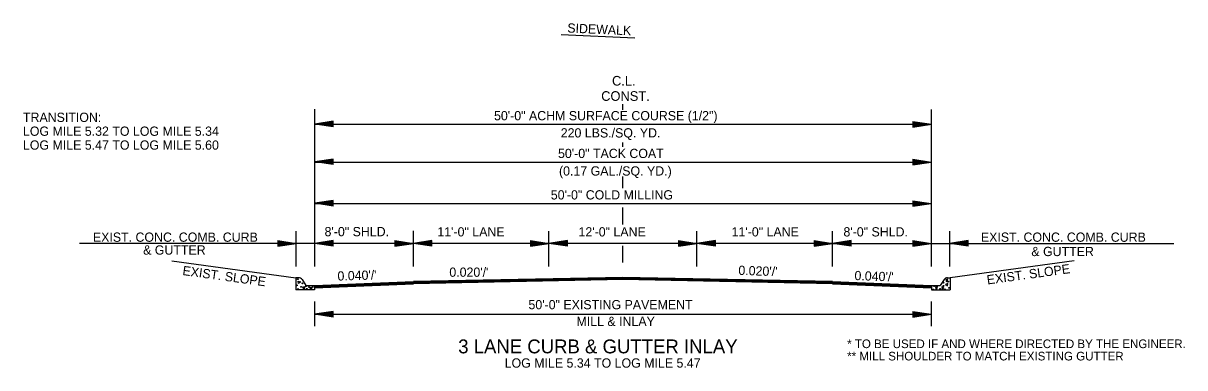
# Model space of a CAD drawing. Extents: x 544199 to 1930787, y -1968972 to 596640.
# Drawn here: x 551509 to 552451, y -1949022 to -1948742 of the extents above; entities that cross this region are included whole.
import ezdxf

# ---------------------------------------------------------------- set-up
doc = ezdxf.new("R2010")
doc.units = 0
for name, color, linetype in [('R_Border', 7, 'Continuous'), ('R_Border Prem', 7, 'Continuous'), ('R_Draft', 7, 'Continuous')]:
    doc.layers.add(name, color=color, linetype=linetype)

msp = doc.modelspace()

# ---------------------------------------------------------------- linework, layer by layer
at = {"layer": 'R_Border'}
msp.add_line((551945.52, -1948751.53), (552005.47, -1948754.13), dxfattribs=at)
at = {"layer": 'R_Draft'}
for p, q in [((551745.7, -1948812.01), (551745.7, -1948939.44)), ((551995.74, -1948812.46), (551995.74, -1948808.05)), ((551760.79, -1948821.8), (551745.79, -1948824.05)), ((551760.79, -1948822.18), (551748.29, -1948824.05)), ((551760.79, -1948822.56), (551750.87, -1948824.05)), ((551760.79, -1948826.3), (551760.79, -1948821.8)), ((552230.79, -1948821.97), (552245.79, -1948824.22)), ((552230.79, -1948821.97), (552230.79, -1948826.47)), ((552230.79, -1948822.35), (552243.28, -1948824.22)), ((552230.79, -1948822.73), (552240.7, -1948824.22)), ((551745.7, -1948824.22), (552245.7, -1948824.22)), ((551760.79, -1948826.3), (551745.79, -1948824.05)), ((551760.79, -1948825.93), (551748.29, -1948824.05)), ((551760.79, -1948825.55), (551750.87, -1948824.05)), ((551760.79, -1948822.94), (551753.37, -1948824.05)), ((551760.79, -1948825.17), (551753.37, -1948824.05)), ((551760.79, -1948823.32), (551755.91, -1948824.05)), ((551760.79, -1948824.78), (551755.91, -1948824.05)), ((551760.79, -1948823.7), (551758.42, -1948824.05)), ((551760.79, -1948824.41), (551758.42, -1948824.05)), ((552230.79, -1948823.11), (552238.21, -1948824.22)), ((552230.79, -1948823.5), (552235.66, -1948824.22)), ((552230.79, -1948823.87), (552233.16, -1948824.22)), ((552230.79, -1948826.47), (552245.79, -1948824.22)), ((552230.79, -1948824.96), (552235.66, -1948824.22)), ((552230.79, -1948825.72), (552240.7, -1948824.22)), ((552230.79, -1948826.1), (552243.28, -1948824.22)), ((552230.79, -1948825.34), (552238.21, -1948824.22)), ((552230.79, -1948824.58), (552233.16, -1948824.22)), ((551995.74, -1948842.59), (551995.74, -1948838.92)), ((551745.7, -1948854.82), (552245.7, -1948854.82)), ((551760.74, -1948852.4), (551745.74, -1948854.65)), ((551760.74, -1948856.9), (551745.74, -1948854.65)), ((551760.74, -1948852.77), (551748.25, -1948854.65)), ((551760.74, -1948856.52), (551748.25, -1948854.65)), ((551760.74, -1948853.16), (551750.83, -1948854.65)), ((551760.74, -1948856.14), (551750.83, -1948854.65)), ((551760.74, -1948853.53), (551753.32, -1948854.65)), ((551760.74, -1948855.77), (551753.32, -1948854.65)), ((551760.74, -1948853.91), (551755.87, -1948854.65)), ((551760.74, -1948855.38), (551755.87, -1948854.65)), ((551760.74, -1948854.3), (551758.37, -1948854.65)), ((551760.74, -1948855), (551758.37, -1948854.65)), ((551760.74, -1948856.9), (551760.74, -1948852.4)), ((552230.74, -1948852.57), (552245.74, -1948854.82)), ((552230.74, -1948852.57), (552230.74, -1948857.07)), ((552230.74, -1948852.95), (552243.24, -1948854.82)), ((552230.74, -1948853.33), (552240.66, -1948854.82)), ((552230.74, -1948853.7), (552238.16, -1948854.82)), ((552230.74, -1948854.09), (552235.62, -1948854.82)), ((552230.74, -1948854.47), (552233.11, -1948854.82)), ((552230.74, -1948857.07), (552245.74, -1948854.82)), ((552230.74, -1948855.56), (552235.62, -1948854.82)), ((552230.74, -1948856.31), (552240.66, -1948854.82)), ((552230.74, -1948856.7), (552243.24, -1948854.82)), ((552230.74, -1948855.94), (552238.16, -1948854.82)), ((552230.74, -1948855.17), (552233.11, -1948854.82)), ((551995.74, -1948875.95), (551995.74, -1948866.65)), ((551745.7, -1948888.42), (552245.7, -1948888.42)), ((551760.74, -1948886), (551745.74, -1948888.25)), ((551760.74, -1948890.5), (551745.74, -1948888.25)), ((551760.74, -1948886.37), (551748.25, -1948888.25)), ((551760.74, -1948890.12), (551748.25, -1948888.25)), ((551760.74, -1948886.76), (551750.83, -1948888.25)), ((551760.74, -1948889.74), (551750.83, -1948888.25)), ((551760.74, -1948887.13), (551753.32, -1948888.25)), ((551760.74, -1948889.37), (551753.32, -1948888.25)), ((551760.74, -1948887.51), (551755.87, -1948888.25)), ((551760.74, -1948888.98), (551755.87, -1948888.25)), ((551760.74, -1948887.9), (551758.37, -1948888.25)), ((551760.74, -1948888.6), (551758.37, -1948888.25)), ((551760.74, -1948890.5), (551760.74, -1948886)), ((552230.74, -1948886.17), (552245.74, -1948888.42)), ((552230.74, -1948886.17), (552230.74, -1948890.67)), ((552230.74, -1948886.54), (552243.24, -1948888.42)), ((552230.74, -1948886.93), (552240.66, -1948888.42)), ((552230.74, -1948887.3), (552238.16, -1948888.42)), ((552230.74, -1948887.69), (552235.62, -1948888.42)), ((552230.74, -1948888.07), (552233.11, -1948888.42)), ((552230.74, -1948890.67), (552245.74, -1948888.42)), ((552230.74, -1948889.15), (552235.62, -1948888.42)), ((552230.74, -1948889.91), (552240.66, -1948888.42)), ((552230.74, -1948890.29), (552243.24, -1948888.42)), ((552230.74, -1948889.54), (552238.16, -1948888.42)), ((552230.74, -1948888.77), (552233.11, -1948888.42)), ((551995.74, -1948905.39), (551995.74, -1948891.57)), ((551730.74, -1948939.61), (551730.74, -1948910.89)), ((551825.74, -1948939.44), (551825.74, -1948910.72)), ((551935.74, -1948939.44), (551935.74, -1948910.89)), ((552055.67, -1948920.78), (552055.67, -1948910.89)), ((552055.74, -1948939.44), (552055.74, -1948910.89)), ((552165.74, -1948939.43), (552165.74, -1948910.88)), ((552260.74, -1948939.61), (552260.74, -1948910.89)), ((551745.74, -1948920.78), (551554.93, -1948920.78)), ((551715.73, -1948918.53), (551730.73, -1948920.78)), ((551715.73, -1948918.53), (551715.73, -1948923.03)), ((551715.73, -1948918.9), (551728.23, -1948920.78)), ((551715.73, -1948919.29), (551725.65, -1948920.78)), ((551715.73, -1948919.66), (551723.15, -1948920.78)), ((551715.73, -1948920.05), (551720.61, -1948920.78)), ((551715.73, -1948920.43), (551718.1, -1948920.78)), ((551715.73, -1948923.03), (551730.73, -1948920.78)), ((551715.73, -1948921.51), (551720.61, -1948920.78)), ((551715.73, -1948922.27), (551725.65, -1948920.78)), ((551715.73, -1948922.65), (551728.23, -1948920.78)), ((551715.73, -1948921.9), (551723.15, -1948920.78)), ((551715.73, -1948921.13), (551718.1, -1948920.78)), ((551760.74, -1948918.53), (551745.74, -1948920.78)), ((551825.74, -1948920.78), (551745.74, -1948920.78)), ((551760.74, -1948923.03), (551745.74, -1948920.78)), ((551760.74, -1948918.9), (551748.25, -1948920.78)), ((551760.74, -1948922.65), (551748.25, -1948920.78)), ((551760.74, -1948919.29), (551750.83, -1948920.78)), ((551760.74, -1948922.27), (551750.83, -1948920.78)), ((551760.74, -1948919.66), (551753.32, -1948920.78)), ((551760.74, -1948921.9), (551753.32, -1948920.78)), ((551760.74, -1948920.04), (551755.87, -1948920.78)), ((551760.74, -1948921.51), (551755.87, -1948920.78)), ((551760.74, -1948920.43), (551758.37, -1948920.78)), ((551760.74, -1948921.13), (551758.37, -1948920.78)), ((551760.74, -1948923.03), (551760.74, -1948918.53)), ((551810.74, -1948918.53), (551825.74, -1948920.78)), ((551810.74, -1948918.53), (551810.74, -1948923.03)), ((551810.74, -1948918.9), (551823.24, -1948920.78)), ((551810.74, -1948919.29), (551820.66, -1948920.78)), ((551810.74, -1948919.66), (551818.16, -1948920.78)), ((551810.74, -1948920.05), (551815.62, -1948920.78)), ((551810.74, -1948920.43), (551813.11, -1948920.78)), ((551810.74, -1948923.03), (551825.74, -1948920.78)), ((551810.74, -1948921.51), (551815.62, -1948920.78)), ((551810.74, -1948922.27), (551820.66, -1948920.78)), ((551810.74, -1948922.65), (551823.24, -1948920.78)), ((551810.74, -1948921.9), (551818.16, -1948920.78)), ((551810.74, -1948921.13), (551813.11, -1948920.78)), ((551840.74, -1948918.53), (551825.74, -1948920.78)), ((551935.74, -1948920.78), (551825.74, -1948920.78)), ((551840.74, -1948923.03), (551825.74, -1948920.78)), ((551840.74, -1948918.9), (551828.25, -1948920.78)), ((551840.74, -1948922.65), (551828.25, -1948920.78)), ((551840.74, -1948919.29), (551830.83, -1948920.78)), ((551840.74, -1948922.27), (551830.83, -1948920.78)), ((551840.74, -1948919.66), (551833.32, -1948920.78)), ((551840.74, -1948921.9), (551833.32, -1948920.78)), ((551840.74, -1948920.04), (551835.87, -1948920.78)), ((551840.74, -1948921.51), (551835.87, -1948920.78)), ((551840.74, -1948920.43), (551838.37, -1948920.78)), ((551840.74, -1948921.13), (551838.37, -1948920.78)), ((551840.74, -1948923.03), (551840.74, -1948918.53)), ((551920.74, -1948918.53), (551935.74, -1948920.78)), ((551920.74, -1948918.53), (551920.74, -1948923.03)), ((551920.74, -1948918.9), (551933.24, -1948920.78)), ((551920.74, -1948919.29), (551930.66, -1948920.78)), ((551920.74, -1948919.66), (551928.16, -1948920.78)), ((551920.74, -1948920.05), (551925.62, -1948920.78)), ((551920.74, -1948920.43), (551923.11, -1948920.78)), ((551920.74, -1948923.03), (551935.74, -1948920.78)), ((551920.74, -1948921.51), (551925.62, -1948920.78)), ((551920.74, -1948922.27), (551930.66, -1948920.78)), ((551920.74, -1948922.65), (551933.24, -1948920.78)), ((551920.74, -1948921.9), (551928.16, -1948920.78)), ((551920.74, -1948921.13), (551923.11, -1948920.78)), ((551950.74, -1948918.53), (551935.74, -1948920.78)), ((552055.74, -1948920.78), (551935.74, -1948920.78)), ((551950.74, -1948923.03), (551935.74, -1948920.78)), ((551950.74, -1948918.9), (551938.25, -1948920.78)), ((551950.74, -1948922.65), (551938.25, -1948920.78)), ((551950.74, -1948919.29), (551940.83, -1948920.78)), ((551950.74, -1948922.27), (551940.83, -1948920.78)), ((551950.74, -1948919.66), (551943.32, -1948920.78)), ((551950.74, -1948921.9), (551943.32, -1948920.78)), ((551950.74, -1948920.04), (551945.87, -1948920.78)), ((551950.74, -1948921.51), (551945.87, -1948920.78)), ((551950.74, -1948920.43), (551948.37, -1948920.78)), ((551950.74, -1948921.13), (551948.37, -1948920.78)), ((551950.74, -1948923.03), (551950.74, -1948918.53)), ((551995.74, -1948936.19), (551995.74, -1948922.9)), ((552040.74, -1948918.53), (552055.74, -1948920.78)), ((552040.74, -1948918.53), (552040.74, -1948923.03)), ((552040.74, -1948918.9), (552053.24, -1948920.78)), ((552040.74, -1948919.29), (552050.66, -1948920.78)), ((552040.74, -1948919.66), (552048.16, -1948920.78)), ((552040.74, -1948920.05), (552045.62, -1948920.78)), ((552040.74, -1948920.43), (552043.11, -1948920.78)), ((552040.74, -1948923.03), (552055.74, -1948920.78)), ((552040.74, -1948921.51), (552045.62, -1948920.78)), ((552040.74, -1948922.27), (552050.66, -1948920.78)), ((552040.74, -1948922.65), (552053.24, -1948920.78)), ((552040.74, -1948921.9), (552048.16, -1948920.78)), ((552040.74, -1948921.13), (552043.11, -1948920.78)), ((552055.67, -1948939.44), (552055.67, -1948920.78)), ((552070.74, -1948918.53), (552055.74, -1948920.78)), ((552165.74, -1948920.78), (552055.74, -1948920.78)), ((552070.74, -1948923.03), (552055.74, -1948920.78)), ((552070.74, -1948918.9), (552058.25, -1948920.78)), ((552070.74, -1948922.65), (552058.25, -1948920.78)), ((552070.74, -1948919.29), (552060.83, -1948920.78)), ((552070.74, -1948922.27), (552060.83, -1948920.78)), ((552070.74, -1948919.66), (552063.32, -1948920.78)), ((552070.74, -1948921.9), (552063.32, -1948920.78)), ((552070.74, -1948920.04), (552065.87, -1948920.78)), ((552070.74, -1948921.51), (552065.87, -1948920.78)), ((552070.74, -1948920.43), (552068.37, -1948920.78)), ((552070.74, -1948921.13), (552068.37, -1948920.78)), ((552070.74, -1948923.03), (552070.74, -1948918.53)), ((552150.74, -1948918.53), (552165.74, -1948920.78)), ((552150.74, -1948918.53), (552150.74, -1948923.03)), ((552150.74, -1948918.9), (552163.24, -1948920.78)), ((552150.74, -1948919.29), (552160.66, -1948920.78)), ((552150.74, -1948919.66), (552158.16, -1948920.78)), ((552150.74, -1948920.05), (552155.62, -1948920.78)), ((552150.74, -1948920.43), (552153.11, -1948920.78)), ((552150.74, -1948923.03), (552165.74, -1948920.78)), ((552150.74, -1948921.51), (552155.62, -1948920.78)), ((552150.74, -1948922.27), (552160.66, -1948920.78)), ((552150.74, -1948922.65), (552163.24, -1948920.78)), ((552150.74, -1948921.9), (552158.16, -1948920.78)), ((552150.74, -1948921.13), (552153.11, -1948920.78)), ((552180.74, -1948918.53), (552165.74, -1948920.78)), ((552165.74, -1948920.78), (552245.74, -1948920.78)), ((552180.74, -1948923.03), (552165.74, -1948920.78)), ((552180.74, -1948918.9), (552168.25, -1948920.78)), ((552180.74, -1948922.65), (552168.25, -1948920.78)), ((552180.74, -1948919.29), (552170.83, -1948920.78)), ((552180.74, -1948922.27), (552170.83, -1948920.78)), ((552180.74, -1948919.66), (552173.32, -1948920.78)), ((552180.74, -1948921.9), (552173.32, -1948920.78)), ((552180.74, -1948920.04), (552175.87, -1948920.78)), ((552180.74, -1948921.51), (552175.87, -1948920.78)), ((552180.74, -1948920.43), (552178.37, -1948920.78)), ((552180.74, -1948921.13), (552178.37, -1948920.78)), ((552180.74, -1948923.03), (552180.74, -1948918.53)), ((552230.74, -1948918.53), (552245.74, -1948920.78)), ((552230.74, -1948918.53), (552230.74, -1948923.03)), ((552230.74, -1948918.9), (552243.24, -1948920.78)), ((552230.74, -1948919.29), (552240.66, -1948920.78)), ((552230.74, -1948919.66), (552238.16, -1948920.78)), ((552230.74, -1948920.05), (552235.62, -1948920.78)), ((552230.74, -1948920.43), (552233.11, -1948920.78)), ((552230.74, -1948923.03), (552245.74, -1948920.78)), ((552230.74, -1948921.51), (552235.62, -1948920.78)), ((552230.74, -1948922.27), (552240.66, -1948920.78)), ((552230.74, -1948922.65), (552243.24, -1948920.78)), ((552230.74, -1948921.9), (552238.16, -1948920.78)), ((552230.74, -1948921.13), (552233.11, -1948920.78)), ((552245.74, -1948920.78), (552442.42, -1948920.78)), ((552275.74, -1948918.53), (552260.74, -1948920.78)), ((552275.74, -1948923.03), (552260.74, -1948920.78)), ((552275.74, -1948918.9), (552263.25, -1948920.78)), ((552275.74, -1948922.65), (552263.25, -1948920.78)), ((552275.74, -1948919.29), (552265.83, -1948920.78)), ((552275.74, -1948922.27), (552265.83, -1948920.78)), ((552275.74, -1948919.66), (552268.32, -1948920.78)), ((552275.74, -1948921.9), (552268.32, -1948920.78)), ((552275.74, -1948920.04), (552270.87, -1948920.78)), ((552275.74, -1948921.51), (552270.87, -1948920.78)), ((552275.74, -1948920.43), (552273.37, -1948920.78)), ((552275.74, -1948921.13), (552273.37, -1948920.78)), ((552275.74, -1948923.03), (552275.74, -1948918.53)), ((551629.98, -1948934.82), (551730.48, -1948948.64)), ((552361.53, -1948934.91), (552261.03, -1948948.73)), ((551732.65, -1948948.6), (551730.48, -1948948.64)), ((551730.48, -1948948.64), (551730.48, -1948958.49)), ((551735.46, -1948950.1), (551738.56, -1948955)), ((551745.48, -1948955), (551825.74, -1948951.79)), ((551745.48, -1948955.3), (551825.75, -1948952.08)), ((551745.48, -1948955.6), (551825.76, -1948952.38)), ((551745.48, -1948955.9), (551825.78, -1948952.68)), ((551745.48, -1948956.2), (551825.79, -1948952.98)), ((551745.48, -1948956.5), (551825.8, -1948953.28)), ((551745.48, -1948956.7), (551825.81, -1948953.48)), ((551995.74, -1948948.39), (551825.74, -1948951.79)), ((551995.75, -1948948.68), (551825.74, -1948952.09)), ((551995.75, -1948948.98), (551825.74, -1948952.39)), ((551995.76, -1948949.28), (551825.74, -1948952.69)), ((551995.76, -1948949.58), (551825.74, -1948952.99)), ((551995.77, -1948949.88), (551825.74, -1948953.29)), ((551995.77, -1948950.08), (551825.74, -1948953.49)), ((552165.74, -1948953.29), (551995.71, -1948949.88)), ((552165.74, -1948953.49), (551995.71, -1948950.08)), ((552165.74, -1948952.69), (551995.72, -1948949.28)), ((552165.74, -1948952.99), (551995.72, -1948949.58)), ((552165.74, -1948952.09), (551995.73, -1948948.68)), ((552165.74, -1948952.39), (551995.73, -1948948.98)), ((552165.74, -1948951.79), (551995.74, -1948948.39)), ((552165.67, -1948953.48), (552246.01, -1948956.7)), ((552165.68, -1948953.28), (552246, -1948956.5)), ((552165.69, -1948952.98), (552246, -1948956.2)), ((552165.7, -1948952.68), (552246, -1948955.9)), ((552165.72, -1948952.38), (552246, -1948955.6)), ((552165.73, -1948952.08), (552246, -1948955.3)), ((552165.74, -1948951.79), (552246, -1948955)), ((552256.05, -1948950.2), (552253.01, -1948955)), ((552258.86, -1948948.7), (552261.03, -1948948.73)), ((552261.03, -1948948.73), (552261.03, -1948958.49)), ((551745.48, -1948958.49), (551730.48, -1948958.49)), ((551738.56, -1948955), (551745.48, -1948955)), ((551745.48, -1948955), (551745.48, -1948956.7)), ((551745.48, -1948955), (551745.48, -1948958.49)), ((552246, -1948955), (552246, -1948956.7)), ((552246, -1948956.7), (552246, -1948955)), ((552246, -1948955), (552246, -1948956.7)), ((552246, -1948956.7), (552246, -1948955)), ((552246, -1948955), (552253.01, -1948955)), ((552246, -1948955), (552246, -1948958.49)), ((552246, -1948958.49), (552261.03, -1948958.49)), ((551745.7, -1948967.99), (551745.7, -1948987.99)), ((552245.7, -1948967.99), (552245.7, -1948987.99)), ((551760.7, -1948975.99), (551745.7, -1948978.24)), ((551745.7, -1948978.24), (552245.7, -1948978.24)), ((551760.7, -1948980.49), (551745.7, -1948978.24)), ((551760.7, -1948976.37), (551748.21, -1948978.24)), ((551760.7, -1948980.12), (551748.21, -1948978.24)), ((551760.7, -1948976.75), (551750.79, -1948978.24)), ((551760.7, -1948979.74), (551750.79, -1948978.24)), ((551760.7, -1948977.13), (551753.29, -1948978.24)), ((551760.7, -1948979.36), (551753.29, -1948978.24)), ((551760.7, -1948977.51), (551755.83, -1948978.24)), ((551760.7, -1948978.97), (551755.83, -1948978.24)), ((551760.7, -1948977.89), (551758.33, -1948978.24)), ((551760.7, -1948978.6), (551758.33, -1948978.24)), ((551760.7, -1948980.49), (551760.7, -1948975.99)), ((552230.7, -1948975.99), (552245.7, -1948978.24)), ((552230.7, -1948975.99), (552230.7, -1948980.49)), ((552230.7, -1948976.37), (552243.2, -1948978.24)), ((552230.7, -1948976.75), (552240.62, -1948978.24)), ((552230.7, -1948977.13), (552238.12, -1948978.24)), ((552230.7, -1948977.52), (552235.58, -1948978.24)), ((552230.7, -1948977.89), (552233.07, -1948978.24)), ((552230.7, -1948980.49), (552245.7, -1948978.24)), ((552230.7, -1948978.98), (552235.58, -1948978.24)), ((552230.7, -1948979.74), (552240.62, -1948978.24)), ((552230.7, -1948980.12), (552243.2, -1948978.24)), ((552230.7, -1948979.36), (552238.12, -1948978.24)), ((552230.7, -1948978.6), (552233.07, -1948978.24))]:
    msp.add_line(p, q, dxfattribs=at)
for points in [[(552245.7, -1948812.18), (552245.7, -1948939.43)], [(551734.42, -1948952.06), (551732.66, -1948953.19), (551732.28, -1948951.42), (551734.19, -1948952.06)], [(552257.08, -1948954.09), (552258.85, -1948955.22), (552259.22, -1948953.45), (552257.32, -1948954.09)], [(552258.03, -1948951.85), (552259.17, -1948950.06), (552257.39, -1948949.7), (552258.03, -1948951.59)], [(551737.23, -1948958.04), (551736.1, -1948956.25), (551737.86, -1948955.88), (551737.23, -1948957.78)], [(551742.89, -1948958.36), (551741.76, -1948956.58), (551743.53, -1948956.21), (551742.89, -1948958.1)], [(552249.72, -1948958.46), (552250.86, -1948956.67), (552249.08, -1948956.3), (552249.72, -1948958.2)], [(552254.85, -1948958.22), (552255.99, -1948956.43), (552254.21, -1948956.07), (552254.85, -1948957.96)]]:
    msp.add_lwpolyline(points, dxfattribs=at)
for centre in [(551731.41, -1948954.8), (551732.04, -1948949.77), (551735.96, -1948953.21), (552255.71, -1948952.67), (552259.47, -1948951.8), (551732.23, -1948957.78), (551734.7, -1948956.07), (551738.89, -1948955.54), (551739.3, -1948957.7), (551741.2, -1948956.32), (551744.13, -1948956.14), (552247.37, -1948958.17), (552248.01, -1948955.42), (552250.21, -1948955.84), (552252.85, -1948957.73), (552255.54, -1948955.23), (552256.81, -1948958.09), (552260.1, -1948956.83)]:
    msp.add_circle(centre, 0.339, dxfattribs=at)
for centre, start, end in [((551732.7, -1948951.86), 32.27564, 91.11964), ((552258.81, -1948951.95), 88.88036, 147.72436)]:
    msp.add_arc(centre, 3.26, start, end, dxfattribs=at)

# ---------------------------------------------------------------- texts
at = {"layer": 'R_Border Prem'}
for s, p in [('* TO BE USED IF AND WHERE DIRECTED BY THE ENGINEER.', (552177.51, -1949005.7)), ('** MILL SHOULDER TO MATCH EXISTING GUTTER', (552177.51, -1949015.7))]:
    msp.add_text(s, height=7, dxfattribs=at).set_placement(p)
at = {"layer": 'R_Draft'}
for s, rotation, p in [('SIDEWALK', 357.45139, (551950.46, -1948749.82)), ('EXIST. SLOPE', 352.16821, (551638.23, -1948946.39)), ("0.040'/'", 1.70227, (551764.34, -1948951.01)), ("0.020'/'", 358.06067, (552089.2, -1948946.31)), ("0.040'/'", 357.81683, (552183.32, -1948950.52)), ('EXIST. SLOPE', 7.83179, (552291.25, -1948954.15))]:
    msp.add_text(s, height=7.5, rotation=rotation, dxfattribs=at).set_placement(p)
for s, height, p in [('C.L.', 7.8, (551986.85, -1948792.85)), ('CONST.', 7.8, (551978.06, -1948805.22)), ('50\'-0" ACHM SURFACE COURSE (1/2")', 7.5, (551891.17, -1948821)), ('TRANSITION:', 7.5, (551509.19, -1948822.32)), ('LOG MILE 5.32 TO LOG MILE 5.34', 7.5, (551509.19, -1948833.57)), ('220 LBS./SQ. YD. ', 7.5, (551945.26, -1948834.94)), ('LOG MILE 5.47 TO LOG MILE 5.60', 7.5, (551509.19, -1948844.82)), ('50\'-0" TACK COAT', 7.5, (551943.06, -1948851.6)), ('(0.17 GAL./SQ. YD.)', 7.5, (551943.85, -1948865.81)), ('50\'-0" COLD MILLING', 7.5, (551937.21, -1948885.2)), ('8\'-0" SHLD.', 7.5, (551753.75, -1948915.01)), ('11\'-0" LANE', 7.5, (551845.21, -1948915.18)), ('12\'-0" LANE', 7.5, (551959.67, -1948915.18)), ('11\'-0" LANE', 7.5, (552083.82, -1948915.18)), ('8\'-0" SHLD.', 7.5, (552174.5, -1948915.18)), ('EXIST. CONC. COMB. CURB', 7.5, (551565.9, -1948919.49)), ('EXIST. CONC. COMB. CURB', 7.5, (552285.96, -1948919.49)), ('& GUTTER ', 7.5, (551606.62, -1948929.89)), ('& GUTTER ', 7.5, (552326.87, -1948931.1)), ("0.020'/'", 7.5, (551854.92, -1948947.88)), ('50\'-0" EXISTING PAVEMENT', 7.5, (551919.08, -1948974.22)), ('MILL & INLAY', 7.5, (551958.03, -1948987.74)), ('3 LANE CURB & GUTTER INLAY', 11.25, (551862.12, -1949009.95)), ('LOG MILE 5.34 TO LOG MILE 5.47', 7.5, (551899.8, -1949021.53))]:
    msp.add_text(s, height=height, dxfattribs=at).set_placement(p)

doc.saveas('drawing.dxf')
